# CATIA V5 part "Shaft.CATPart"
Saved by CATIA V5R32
Part number: Shaft
Bounding box of the stored display mesh (mm): x -10.997 to 10.997, y 0 to 134, z -10.875 to 10.875
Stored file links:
  D:\PROJECTS\Project 2022\CATIA V5 6R 2022\Resources\Part Files\c14_catia_v5_6r2022_prt\c14-catia-v5-6r2022-figr-14-26 & 27\Part & Asm\Shaft.CATPart
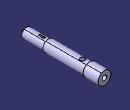
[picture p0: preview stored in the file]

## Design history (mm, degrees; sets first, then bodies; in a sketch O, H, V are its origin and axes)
Body1 (main body)
  Sketch1 on yz-plane, origin (0, 0, 0), H (0, 1, 0), V (0, 0, 1)
    line L1 (0, 0) -> (0, 8)
    line L2 (0, 8) -> (39, 8)
    line L3 (39, 8) -> (39, 9.5)
    line L4 (39, 9.5) -> (109, 9.5)
    line L5 (109, 9.5) -> (109, 11)
    line L6 (109, 11) -> (134, 11)
    line L7 (134, 11) -> (134, 0)
    point P7 (134, 0)
    line L8 (134, 0) -> (0, 0)
    length L1 = 8
    length L8 = 134
    length L7 = 11
    distance L4 L8 = 9.5
    length L6 = 25
    length L4 = 70
    vertical: L1 V, L3 V, L5 V, L7 V
    horizontal: L2 H, L4 H, L6 H, L8 H
    coincidence: P7 H
  Shaft1: profile Sketch1, axis edge of Sketch1, angle 360
  Chamfer1: length 1.5, angle 45, on 1 edge
  Sketch2 on xy-plane, origin (0, 0, 0), H (1, 0, 0), V (0, 1, 0)
    circle A1 centre (0, 97) radius 4.15
    point P1 (0, 97)
    reference projected line E1 (-11, 109) -> (11, 109) from edge of Shaft1
    radius A1 = 4.15
    distance E1 P1 = 12
    coincidence: P1 V
  Pocket1: profile Sketch2, direction (0, 0, -1), length 20, mirrored extent
  Sketch3 on face of Shaft1, origin (0, 134, 0), H (-1, 0, 0), V (0, 0, 1)
    circle A1 centre (0, 0) radius 4.15
    radius A1 = 4.15
  Pocket2: profile Sketch3, direction (0, -1, 0), length 44
  Sketch4 on yz-plane, origin (0, 0, 0), H (0, 1, 0), V (0, 0, 1)
    point P1 (23, 8)
    line L1 (23, 8) -> (33, 8)
    arc A1 centre (28, 12.899) radius 7 from (23, 8) to (33, 8) ccw
    reference projected line E1 (39, -9.5) -> (39, 9.5) from edge of Shaft1
    length L1 = 10
    distance L1 H = 8
    distance P1 E1 = 16
    radius A1 = 7
    horizontal: L1 H
  Pocket3: profile Sketch4, direction (-1, 0, 0), length 1.6, mirrored extent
